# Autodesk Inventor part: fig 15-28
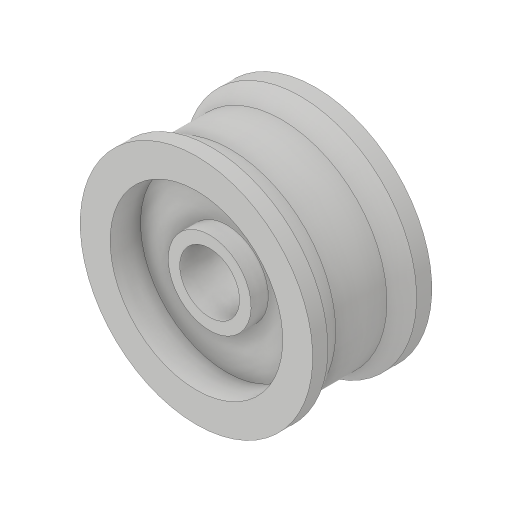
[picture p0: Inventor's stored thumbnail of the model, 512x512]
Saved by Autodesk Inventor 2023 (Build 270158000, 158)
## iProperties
Created: 2018-03
Part Number: fig 15-28
Material: Generic
Document SubType Name: Modeling
Designer: CADCIM 00
Density: 1 g/cm^3
Appearance: Default
Author: CADCIM 00
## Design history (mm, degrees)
sketch "Sketch1"
  geometry: L1 (3.327, 5.31)-(3.327, -4.99); L2 (3.327, -4.99)-(4.606, -4.99); L3 (4.606, -4.99)-(4.606, -3.071); L4 (4.606, -3.071)-(9.597, -3.071); L5 (9.597, -3.071)-(9.597, -6.462); L6 (9.597, -6.462)-(12.924, -6.462); L7 (12.924, -6.462)-(12.924, -4.766); L8 (12.924, -4.766)-(11.708, -2.687); L9 (11.708, -2.687)-(11.708, 0.16); L10 (11.708, 0.16)-(3.327, 0.16); L11 (3.327, 5.31)-(4.606, 5.31); L12 (4.606, 5.31)-(4.606, 3.391); L13 (4.606, 3.391)-(9.597, 3.391); L14 (9.597, 3.391)-(9.597, 6.782); L15 (9.597, 6.782)-(12.924, 6.782); L16 (12.924, 6.782)-(12.924, 5.086); L17 (12.924, 5.086)-(11.708, 3.007); L18 (11.708, 3.007)-(11.708, 0.16); L19 (0, 7.901)-(0, -9.532); 1 further point
  constraints: 38 end point, 7 symmetric about line, 6 perpendicular, 2 vertical, 1 midpoint, 1 parallel
revolve "Revolution1" sketch "Sketch1" stored, may be unused: angle "d0" = 90 deg
body "Solid1"
